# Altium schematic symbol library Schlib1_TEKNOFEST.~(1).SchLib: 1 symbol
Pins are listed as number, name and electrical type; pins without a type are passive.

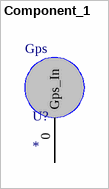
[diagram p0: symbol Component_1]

## Component_1
designator U?
pins: 0 Gps_In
